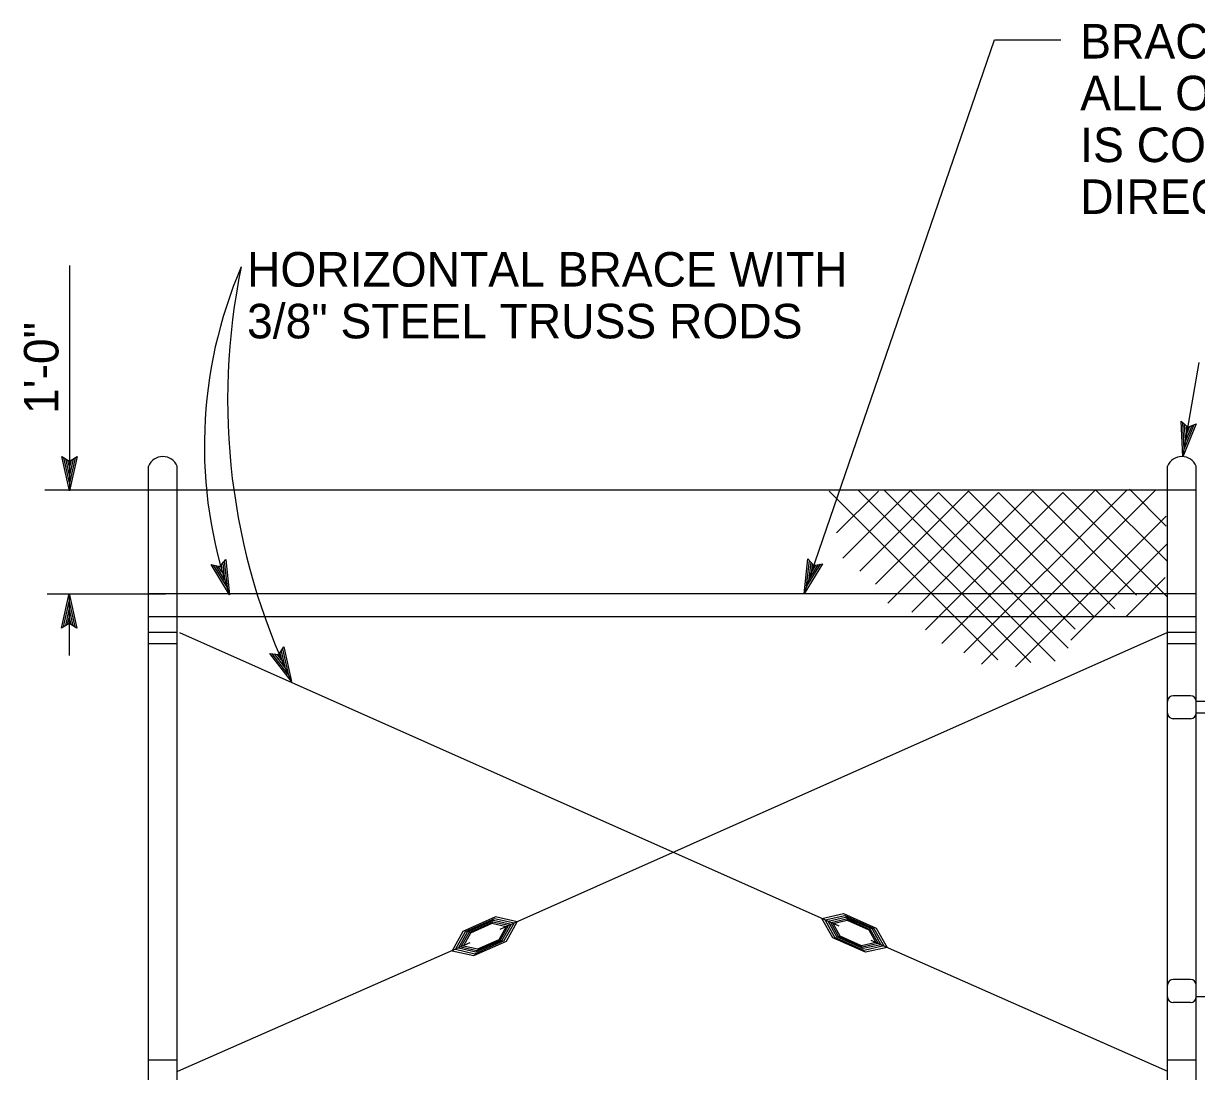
# Model space of a CAD drawing. Extents: x -123486 to -116575, y -107066 to -101122.
# Drawn here: x -118563.5 to -118359.8, y -102006.5 to -101824.4 of the extents above; entities that cross this region are included whole.
import ezdxf

# ---------------------------------------------------------------- set-up
doc = ezdxf.new("R2010")
doc.units = 0
for name, color, linetype in [('G-MARK', 7, 'Continuous'), ('G-TEXT', 7, 'Continuous'), ('Misc CnstDet(22)', 7, 'Continuous'), ('Nongeo Data(60)', 7, 'Continuous')]:
    doc.layers.add(name, color=color, linetype=linetype)

msp = doc.modelspace()

# ---------------------------------------------------------------- linework, layer by layer
at = {"layer": 'G-MARK'}
for p, q in [((-118394.83, -101827.25), (-118383.32, -101827.25)), ((-118555.49, -101866.45), (-118555.52, -101905.63)), ((-118362.16, -101899.67), (-118362.44, -101893.53)), ((-118362.44, -101893.53), (-118362.44, -101893.53)), ((-118362.44, -101893.53), (-118361.27, -101894.54)), ((-118359.81, -101893.98), (-118362.16, -101899.67)), ((-118361.92, -101898.29), (-118362.13, -101893.82)), ((-118360.2, -101894.14), (-118361.92, -101898.31)), ((-118361.68, -101896.94), (-118361.82, -101894.05)), ((-118360.59, -101894.3), (-118361.68, -101896.94)), ((-118361.45, -101895.58), (-118361.5, -101894.35)), ((-118360.96, -101894.42), (-118361.45, -101895.58)), ((-118361.27, -101894.54), (-118359.81, -101893.98)), ((-118359.81, -101893.98), (-118359.81, -101893.98)), ((-118362.16, -101899.67), (-118362.16, -101899.67)), ((-118427.93, -101923.5), (-118427.24, -101917.39)), ((-118427.48, -101922.18), (-118426.97, -101917.73)), ((-118427.24, -101917.39), (-118427.24, -101917.39)), ((-118427.24, -101917.39), (-118426.24, -101918.58)), ((-118427.03, -101920.89), (-118426.7, -101918.01)), ((-118424.71, -101918.26), (-118427.93, -101923.5)), ((-118425.12, -101918.35), (-118427.48, -101922.19)), ((-118425.53, -101918.45), (-118427.03, -101920.89)), ((-118426.58, -101919.58), (-118426.44, -101918.35)), ((-118425.92, -101918.51), (-118426.58, -101919.58)), ((-118426.24, -101918.58), (-118424.71, -101918.26)), ((-118424.71, -101918.26), (-118424.71, -101918.26)), ((-118555.54, -101923.44), (-118555.55, -101934.22)), ((-118427.93, -101923.5), (-118427.93, -101923.5))]:
    msp.add_line(p, q, dxfattribs=at)
for points in [[(-118427.93, -101923.5), (-118394.83, -101827.25), (-118394.83, -101827.25)], [(-118362.16, -101899.67), (-118359.31, -101883.3)]]:
    msp.add_lwpolyline(points, dxfattribs=at)
for centre, radius, start, end in [((-118453.52, -101897.76), 78.56, 156.7153, 199.2421), ((-118414.49, -101889.8), 113.56, 168.2679, 205.5228)]:
    msp.add_arc(centre, radius, start, end, dxfattribs=at)
at = {"layer": 'G-TEXT'}
for p, q in [((-118555.52, -101905.63), (-118556.85, -101899.63)), ((-118556.85, -101899.63), (-118556.85, -101899.63)), ((-118556.85, -101899.63), (-118555.52, -101900.43)), ((-118555.53, -101904.24), (-118556.49, -101899.86)), ((-118555.52, -101900.43), (-118554.18, -101899.63)), ((-118554.18, -101899.63), (-118555.52, -101905.63)), ((-118554.53, -101899.85), (-118555.52, -101904.25)), ((-118554.18, -101899.63), (-118554.18, -101899.63)), ((-118555.52, -101902.87), (-118556.14, -101900.04)), ((-118555.52, -101901.49), (-118555.78, -101900.28)), ((-118554.89, -101900.08), (-118555.52, -101902.87)), ((-118555.24, -101900.26), (-118555.52, -101901.49)), ((-118555.52, -101905.63), (-118555.52, -101905.63)), ((-118529.38, -101918.74), (-118528.37, -101917.55)), ((-118528.9, -101918.2), (-118528.59, -101921.04)), ((-118528.64, -101917.87), (-118528.14, -101922.35)), ((-118528.37, -101917.55), (-118528.37, -101917.55)), ((-118528.37, -101917.55), (-118527.69, -101923.66)), ((-118527.69, -101923.66), (-118530.9, -101918.41)), ((-118530.9, -101918.41), (-118530.9, -101918.41)), ((-118530.9, -101918.41), (-118529.38, -101918.74)), ((-118528.15, -101922.34), (-118530.48, -101918.52)), ((-118528.59, -101921.04), (-118530.1, -101918.57)), ((-118529.03, -101919.74), (-118529.68, -101918.68)), ((-118529.17, -101918.48), (-118529.03, -101919.74)), ((-118556.89, -101929.44), (-118555.54, -101923.44)), ((-118555.54, -101923.44), (-118555.54, -101923.44)), ((-118555.54, -101923.44), (-118554.22, -101929.44)), ((-118527.69, -101923.66), (-118527.69, -101923.66)), ((-118556.53, -101929.23), (-118555.54, -101924.82)), ((-118556.17, -101928.99), (-118555.55, -101926.21)), ((-118555.55, -101926.21), (-118554.92, -101929.03)), ((-118555.54, -101924.83), (-118554.58, -101929.21)), ((-118555.83, -101928.82), (-118555.55, -101927.59)), ((-118555.55, -101927.59), (-118555.28, -101928.8)), ((-118555.55, -101928.64), (-118556.89, -101929.44)), ((-118556.89, -101929.44), (-118556.89, -101929.44)), ((-118554.22, -101929.44), (-118555.55, -101928.64)), ((-118554.22, -101929.44), (-118554.22, -101929.44)), ((-118516.97, -101938.73), (-118520.7, -101933.85)), ((-118520.7, -101933.85), (-118520.7, -101933.85)), ((-118520.7, -101933.85), (-118519.16, -101934.01)), ((-118517.56, -101937.47), (-118520.28, -101933.91)), ((-118518.13, -101936.22), (-118519.89, -101933.92)), ((-118518.71, -101934.97), (-118519.46, -101933.99)), ((-118519.16, -101934.01), (-118518.28, -101932.72)), ((-118518.98, -101933.74), (-118518.71, -101934.97)), ((-118518.74, -101933.43), (-118518.13, -101936.22)), ((-118518.51, -101933.07), (-118517.55, -101937.48)), ((-118518.28, -101932.72), (-118518.28, -101932.72)), ((-118518.28, -101932.72), (-118516.97, -101938.73)), ((-118516.97, -101938.73), (-118516.97, -101938.73))]:
    msp.add_line(p, q, dxfattribs=at)
at = {"layer": 'Nongeo Data(60)'}
for p, q in [((-118541.8, -102055.5), (-118541.8, -101901.31)), ((-118536.8, -102055.5), (-118536.8, -101901.31)), ((-118364.8, -101988.23), (-118364.8, -101901.31)), ((-118359.8, -101988.23), (-118359.8, -101901.31)), ((-118541.62, -101905.5), (-118559.79, -101905.5)), ((-118541.8, -102055.5), (-118541.8, -101905.5)), ((-118359.8, -101905.5), (-118541.62, -101905.5)), ((-118394.25, -101934.98), (-118423.56, -101905.67)), ((-118422.26, -101912.91), (-118415.02, -101905.67)), ((-118421.19, -101917.3), (-118409.32, -101905.43)), ((-118388.56, -101935.45), (-118418.58, -101905.43)), ((-118418.22, -101919.55), (-118404.58, -101905.9)), ((-118415.5, -101921.81), (-118399.36, -101905.67)), ((-118384.29, -101935.22), (-118414.07, -101905.43)), ((-118413.36, -101925.13), (-118394.14, -101905.9)), ((-118382.03, -101932.96), (-118409.56, -101905.43)), ((-118409.21, -101926.67), (-118388.2, -101905.67)), ((-118406.83, -101929.76), (-118382.98, -101905.9)), ((-118380.84, -101929.64), (-118404.58, -101905.9)), ((-118403.98, -101932.13), (-118377.28, -101905.43)), ((-118400.16, -101933.76), (-118371.83, -101905.44)), ((-118377.64, -101927.38), (-118399.36, -101905.67)), ((-118397.1, -101935.69), (-118366.84, -101905.43)), ((-118373.96, -101926.08), (-118394.14, -101905.9)), ((-118370.16, -101923.7), (-118388.2, -101905.67)), ((-118364.82, -101924.06), (-118382.98, -101905.9)), ((-118364.82, -101917.89), (-118377.28, -101905.43)), ((-118365.02, -101911.73), (-118371.42, -101905.33)), ((-118391.17, -101936.16), (-118365.04, -101910.03)), ((-118381.56, -101931.54), (-118364.78, -101914.76)), ((-118371.94, -101927.38), (-118365.23, -101920.67)), ((-118559.4, -101923.48), (-118538.81, -101923.48)), ((-118359.8, -101923.5), (-118541.8, -101923.5)), ((-118359.8, -101927.5), (-118541.8, -101927.5)), ((-118536.8, -101930.2), (-118541.8, -101930.2)), ((-118536.39, -101930.2), (-118421.86, -101981.18)), ((-118364.8, -101930.2), (-118480.75, -101981.8)), ((-118359.8, -101930.2), (-118364.8, -101930.2)), ((-118536.8, -101932.2), (-118541.8, -101932.2)), ((-118359.8, -101932.2), (-118364.8, -101932.2)), ((-118364.8, -101941.2), (-118364.8, -101938.93)), ((-118359.8, -101941.18), (-118359.8, -101938.93)), ((-118364.8, -101946.85), (-118364.8, -101941.15)), ((-118364.8, -101944.2), (-118364.8, -101942.2)), ((-118360.8, -101941.2), (-118363.8, -101941.2)), ((-118359.8, -101946.85), (-118359.8, -101941.18)), ((-118353.67, -101942.2), (-118359.8, -101942.2)), ((-118359.8, -101944.2), (-118359.8, -101942.2)), ((-118353.67, -101944.2), (-118359.8, -101944.2)), ((-118360.8, -101945.2), (-118363.8, -101945.2)), ((-118424.84, -101979.88), (-118421.06, -101979.03)), ((-118421.06, -101979.03), (-118415.4, -101981.55)), ((-118481.5, -101979.6), (-118487.17, -101982.13)), ((-118481.69, -101979.94), (-118486.78, -101982.21)), ((-118481.85, -101980.25), (-118486.44, -101982.29)), ((-118482, -101980.52), (-118486.13, -101982.36)), ((-118482.13, -101980.77), (-118485.85, -101982.42)), ((-118479.66, -101981.32), (-118482.13, -101980.77)), ((-118479.25, -101981.14), (-118482, -101980.52)), ((-118478.8, -101980.94), (-118481.85, -101980.25)), ((-118478.29, -101980.71), (-118481.69, -101979.94)), ((-118477.73, -101980.46), (-118481.5, -101979.6)), ((-118480.9, -101983.54), (-118479.66, -101981.32)), ((-118480.63, -101983.6), (-118479.25, -101981.14)), ((-118480.33, -101983.67), (-118478.8, -101980.94)), ((-118480, -101983.74), (-118478.29, -101980.71)), ((-118479.62, -101983.83), (-118477.73, -101980.46)), ((-118422.94, -101983.25), (-118424.84, -101979.88)), ((-118424.27, -101980.13), (-118420.87, -101979.37)), ((-118422.57, -101983.17), (-118424.27, -101980.13)), ((-118423.76, -101980.36), (-118420.7, -101979.67)), ((-118422.22, -101983.09), (-118423.76, -101980.36)), ((-118423.3, -101980.57), (-118420.55, -101979.95)), ((-118421.92, -101983.03), (-118423.3, -101980.57)), ((-118422.89, -101980.75), (-118420.41, -101980.19)), ((-118421.64, -101982.96), (-118422.89, -101980.75)), ((-118420.87, -101979.37), (-118415.78, -101981.64)), ((-118420.7, -101979.67), (-118416.12, -101981.71)), ((-118420.55, -101979.95), (-118416.42, -101981.79)), ((-118420.41, -101980.19), (-118416.7, -101981.85)), ((-118487.17, -101982.13), (-118489.06, -101985.5)), ((-118486.78, -101982.21), (-118488.49, -101985.25)), ((-118486.44, -101982.29), (-118487.97, -101985.02)), ((-118486.13, -101982.36), (-118487.51, -101984.82)), ((-118485.85, -101982.42), (-118487.09, -101984.63)), ((-118417.28, -101985.77), (-118422.94, -101983.25)), ((-118417.47, -101985.44), (-118422.57, -101983.17)), ((-118417.64, -101985.13), (-118422.22, -101983.09)), ((-118417.79, -101984.86), (-118421.92, -101983.03)), ((-118417.93, -101984.62), (-118421.64, -101982.96)), ((-118416.7, -101981.85), (-118415.45, -101984.06)), ((-118416.42, -101981.79), (-118415.04, -101984.24)), ((-118416.12, -101981.71), (-118414.58, -101984.45)), ((-118415.78, -101981.64), (-118414.08, -101984.67)), ((-118415.4, -101981.55), (-118413.51, -101984.92)), ((-118485.96, -101984.12), (-118536.76, -102006.47)), ((-118488.49, -101985.25), (-118485.09, -101986.01)), ((-118487.97, -101985.02), (-118484.92, -101985.71)), ((-118487.51, -101984.82), (-118484.76, -101985.44)), ((-118487.09, -101984.63), (-118484.61, -101985.19)), ((-118485.29, -101986.35), (-118479.62, -101983.83)), ((-118485.09, -101986.01), (-118480, -101983.74)), ((-118484.92, -101985.71), (-118480.33, -101983.67)), ((-118484.76, -101985.44), (-118480.63, -101983.6)), ((-118484.61, -101985.19), (-118480.9, -101983.54)), ((-118415.45, -101984.06), (-118417.93, -101984.62)), ((-118415.04, -101984.24), (-118417.79, -101984.86)), ((-118414.58, -101984.45), (-118417.64, -101985.13)), ((-118414.08, -101984.67), (-118417.47, -101985.44)), ((-118413.51, -101984.92), (-118417.28, -101985.77)), ((-118416.32, -101983.65), (-118364.78, -102006.42)), ((-118489.06, -101985.5), (-118485.29, -101986.35)), ((-118364.8, -101990.49), (-118364.8, -101988.23)), ((-118364.8, -101996.14), (-118364.8, -101988.23)), ((-118359.8, -101990.48), (-118359.8, -101988.23)), ((-118359.8, -101996.14), (-118359.8, -101988.23)), ((-118364.8, -101996.14), (-118364.8, -101990.45)), ((-118364.8, -101993.5), (-118364.8, -101991.5)), ((-118360.8, -101990.5), (-118363.8, -101990.5)), ((-118359.8, -101996.14), (-118359.8, -101990.48)), ((-118359.8, -101993.5), (-118359.8, -101991.5)), ((-118353.67, -101993.5), (-118359.8, -101993.5)), ((-118360.8, -101994.5), (-118363.8, -101994.5)), ((-118364.8, -102055.5), (-118364.8, -101996.14)), ((-118359.8, -102055.5), (-118359.8, -101996.14)), ((-118536.8, -102004.5), (-118541.8, -102004.5)), ((-118359.8, -102004.5), (-118364.8, -102004.5))]:
    msp.add_line(p, q, dxfattribs=at)
for centre, radius, start, end in [((-118539.3, -101902.38), 2.72, 23.2888, 156.7112), ((-118362.3, -101902.38), 2.72, 23.2888, 156.7112), ((-118363.8, -101942.2), 1, 90, 180), ((-118360.8, -101942.2), 1, 0, 90), ((-118363.8, -101944.2), 1, 180, 270), ((-118360.8, -101944.2), 1, 270, 0), ((-118363.8, -101991.5), 1, 90, 180), ((-118360.8, -101991.5), 1, 0, 90), ((-118363.8, -101993.5), 1, 180, 270), ((-118360.8, -101993.5), 1, 270, 0)]:
    msp.add_arc(centre, radius, start, end, dxfattribs=at)

# ---------------------------------------------------------------- texts
at = {"layer": 'Misc CnstDet(22)'}
for s, p in [('BRACE TO BE REMOVED AFTER', (-118379.96, -101830.5)), ('ALL OTHER FENCE CONSTRUCTION', (-118379.96, -101839.5)), ('IS COMPLETED UNLESS OTHERWISE', (-118379.96, -101848.5)), ('DIRECTED BY THE ENGINEER', (-118379.96, -101857.5)), ('HORIZONTAL BRACE WITH', (-118524.67, -101870.12)), ('3/8" STEEL TRUSS RODS', (-118524.67, -101879.12))]:
    msp.add_text(s, height=6, dxfattribs=at).set_placement(p)
at = {"layer": 'Nongeo Data(60)'}
msp.add_text('1\'-0"', height=6, rotation=90, dxfattribs=at).set_placement((-118557.42, -101892.25))

doc.saveas('drawing.dxf')
